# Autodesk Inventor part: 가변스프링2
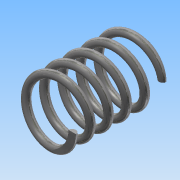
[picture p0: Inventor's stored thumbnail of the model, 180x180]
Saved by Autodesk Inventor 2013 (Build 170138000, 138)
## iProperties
Created: 2014-12
Part Number: 가변스프링2
Material: 강철, 탄소
Document SubType Name: Modeling
Designer: Administrator
Density: 7.87 g/cm^3
Mass: 18.8852 g
Surface Area: 32.5231 cm^2
Volume: 2.39964 cm^3
Author: Administrator
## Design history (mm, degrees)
sketch "스케치1"
  geometry: L1 (0, 0)-(0, 36.261); L2 (0, 36.261)-(11, 36.261); L3 (0, 0)-(11, 0); C1 r 1.5 at (11, 0)
  constraints: 6 end point, 2 parallel, 1 centre point, 1 coincident, 1 perpendicular, 1 vertical
  dimensions: "d0" = 36.2612 distance of L1.start L1.end (derived); "d1" = 11 distance of L1.end L2.end; "d2" = 3 diameter of C1
feature "코일1" sketch "스케치1" pitch "d3" = 10; turns "d5" = 5; dims "d4" = 36.2612 (= d0), "d6" = 0, angle "d7" = 90 deg, angle "d8" = 90 deg, "d9" = 0, "d10" = 0
sketch "스케치2"
  geometry: L1 (36.261, 16.5)-(0, 16.5); L2 (0, 16.5)-(0, -16.5); L3 (0, -16.5)-(36.261, -16.5); L4 (36.261, -16.5)-(36.261, 16.5); 2 further points
  constraints: 8 end point, 2 coincident, 2 parallel, 1 horizontal, 1 midpoint, 1 perpendicular
  dimensions: "d11" = 36.2612 distance of L2.end L3.end (derived); "d13" = 33 distance of L3.end L1.start
extrude "돌출1" sketch "스케치2" stored distance "d14" = 0; taper "d15" = 0 deg
node "솔리드1"
